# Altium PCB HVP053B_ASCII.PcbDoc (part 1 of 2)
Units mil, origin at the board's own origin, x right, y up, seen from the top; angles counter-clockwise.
Board outline 3600 x 3000 mil, 4 copper layers (Top Layer, Signal Layer 1, Signal Layer 2, Bottom Layer), stack 39.6 mil thick; 143 components, 62 nets, 279 pads, 97 vias.
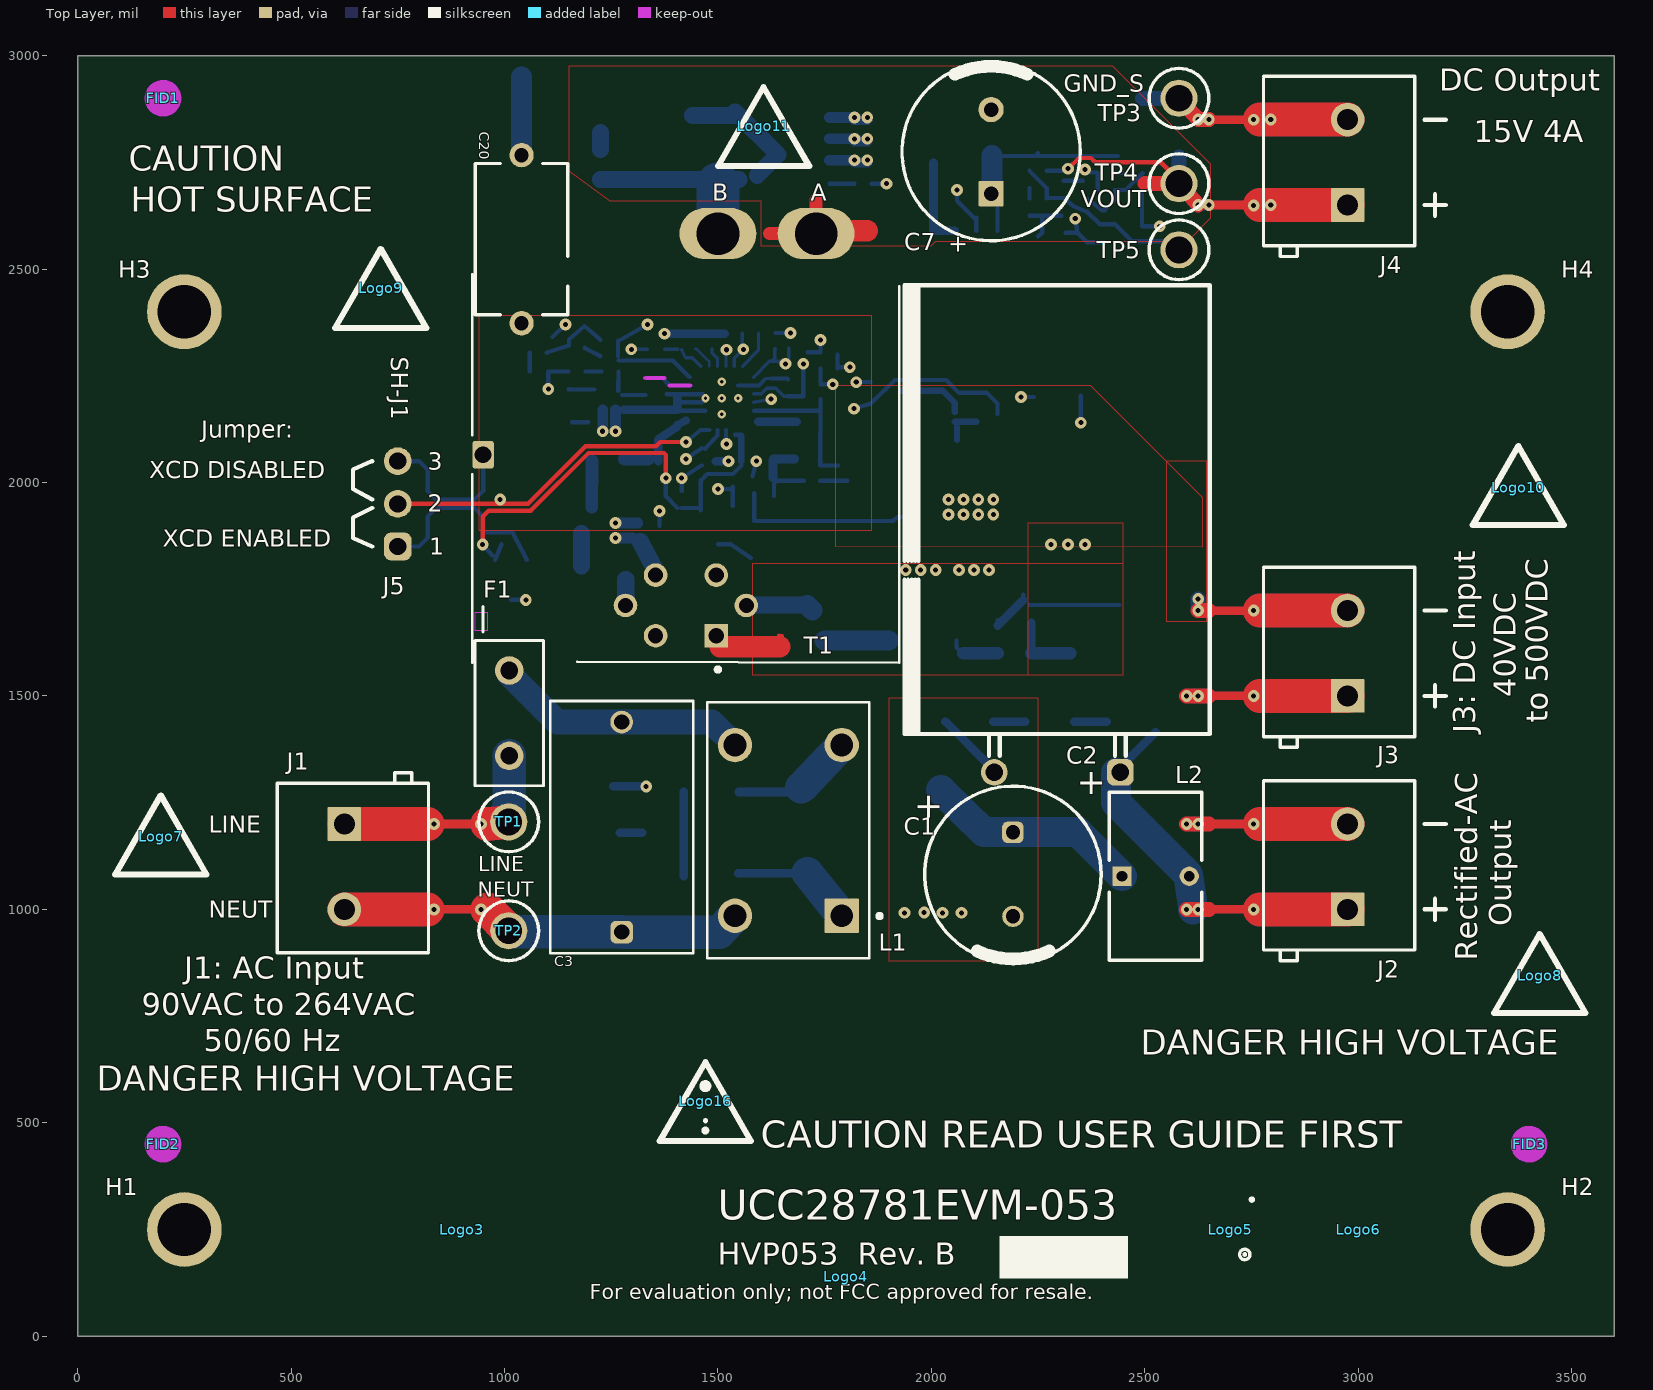
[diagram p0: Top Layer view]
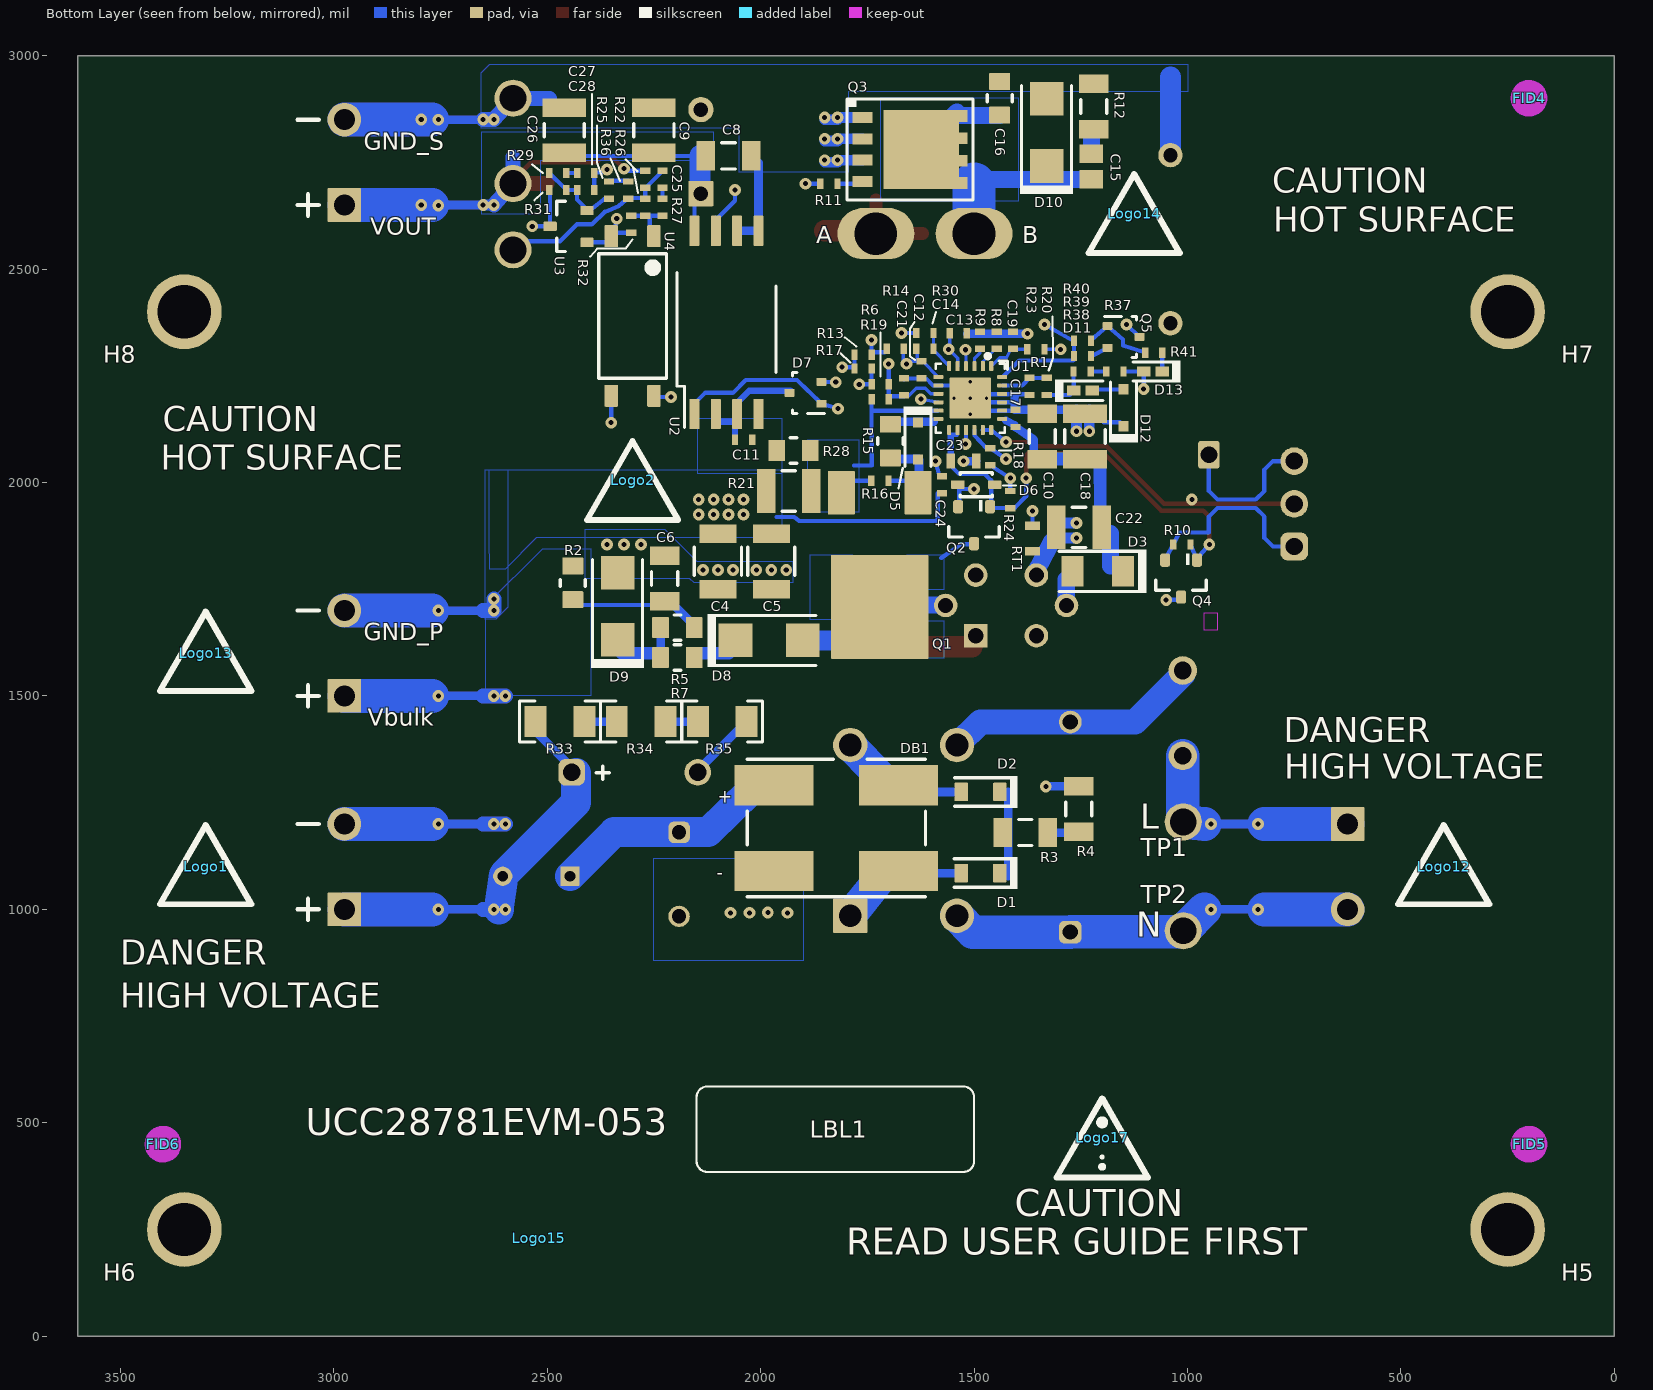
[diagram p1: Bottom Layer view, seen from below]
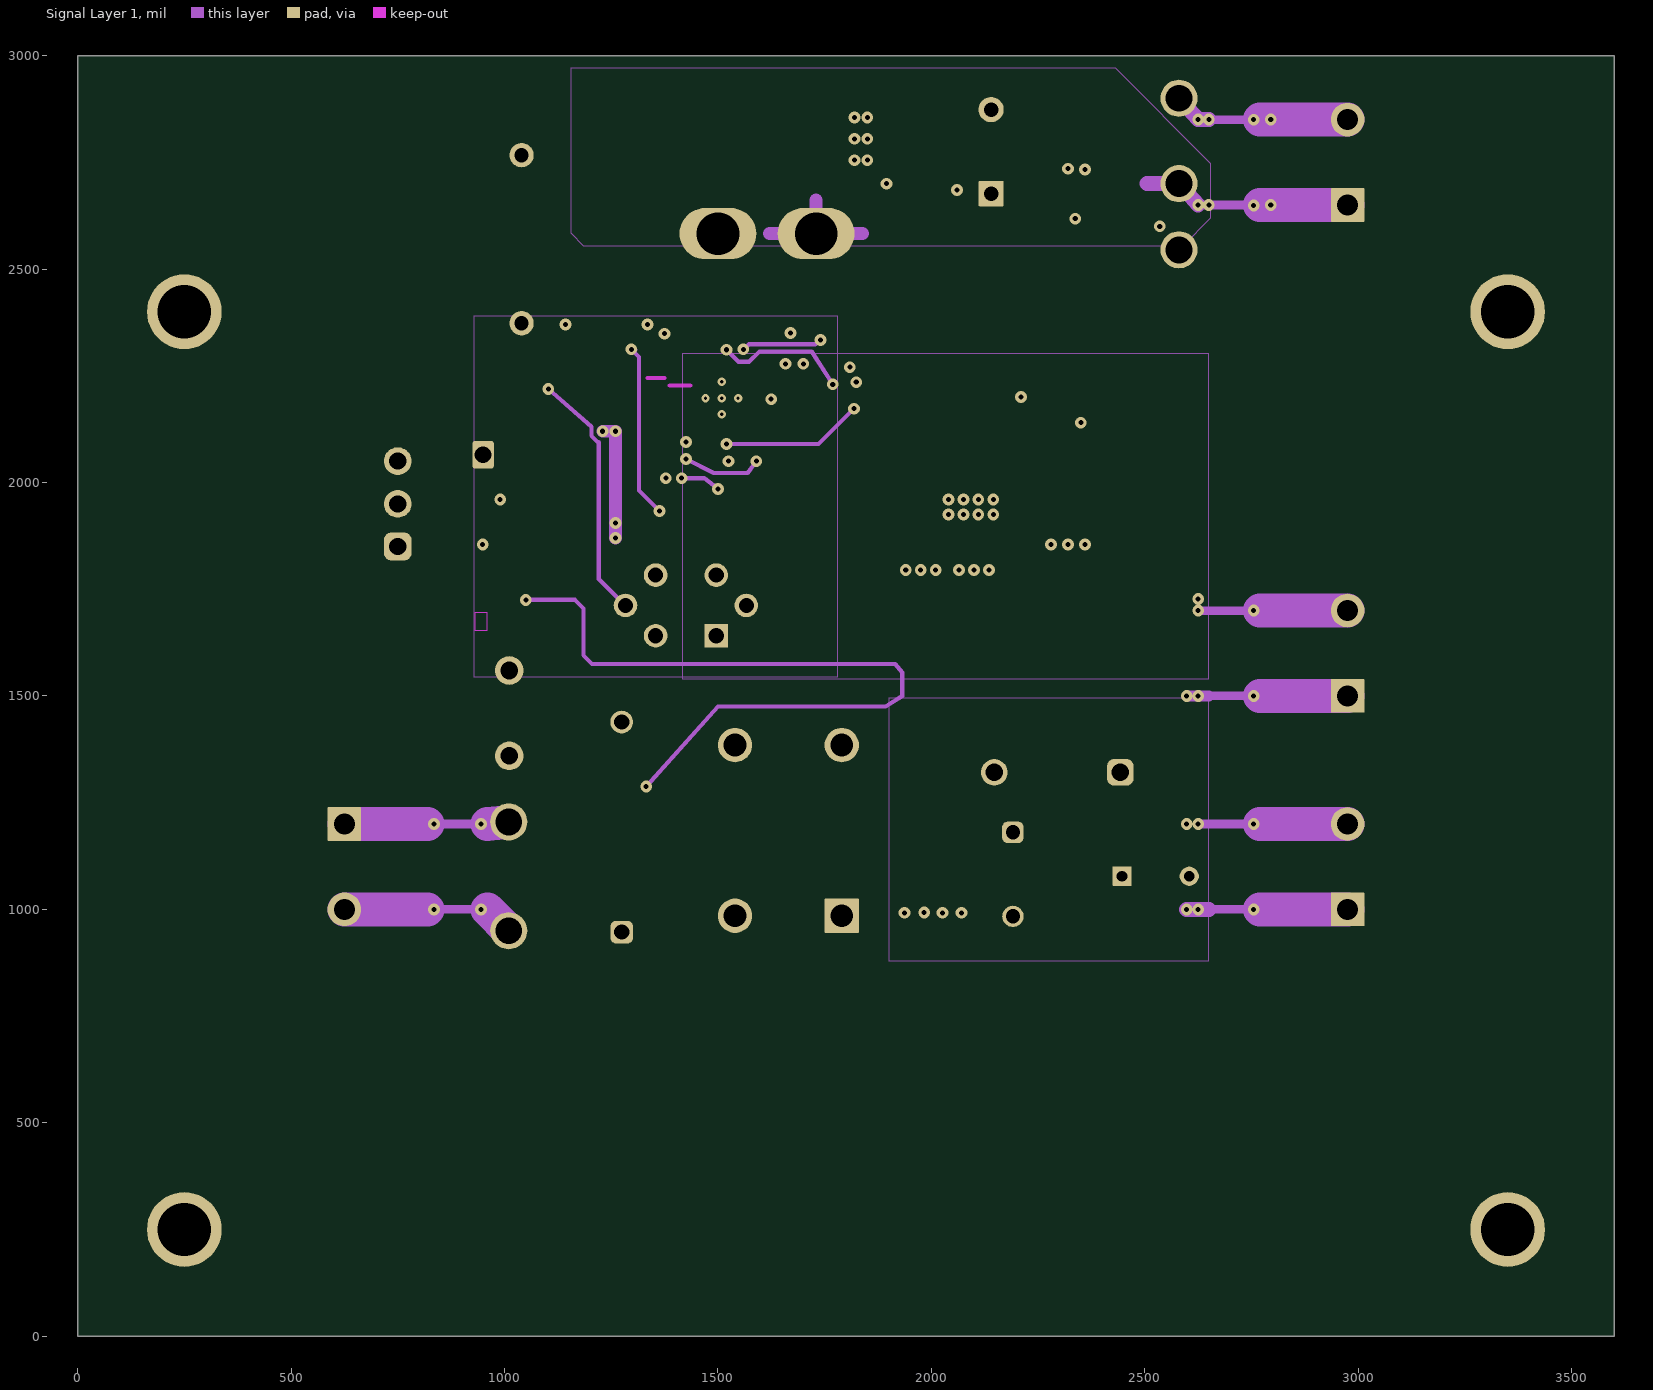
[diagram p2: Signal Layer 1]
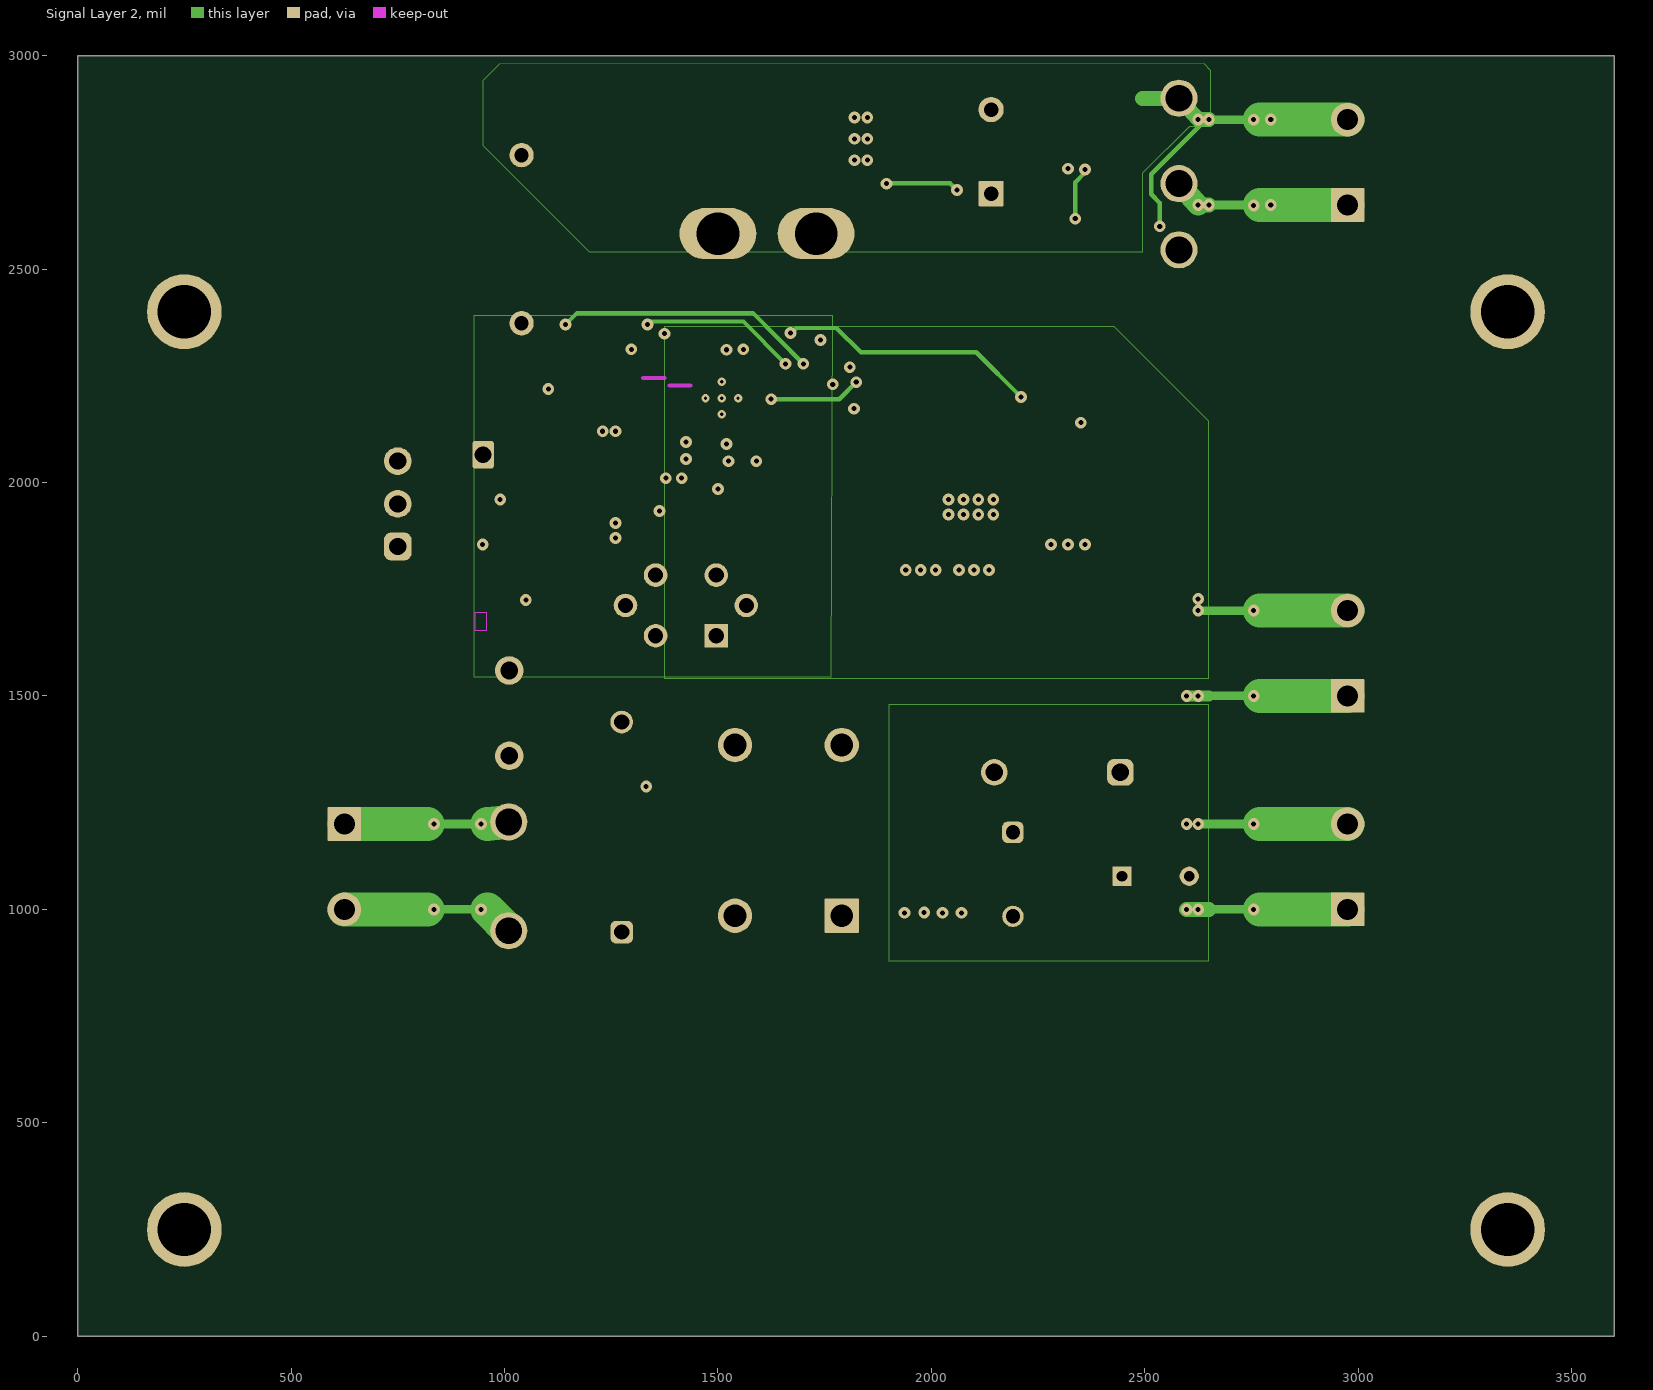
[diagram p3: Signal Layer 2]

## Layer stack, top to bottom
Top Solder: solder mask 0.4, Solder Resist, Dk 3.5
Top Layer: signal copper 1.4
Dielectric 1: prepreg 8, FR-4, Dk 4.2
Signal Layer 1: signal copper 1.4
Dielectric 2: core 18, FR-4, Dk 4.2
Signal Layer 2: signal copper 1.4
Dielectric 3: prepreg 8, FR-4, Dk 4.2
Bottom Layer: signal copper 1.4
Bottom Solder: solder mask 0.4, Solder Resist, Dk 3.5

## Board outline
0,0 3600,0 3600,3000 0,3000

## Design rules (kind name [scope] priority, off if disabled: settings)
AcuteAngle [All] p0: scope1count=1 scope1_0_kind=Board scope1_0_value=Board scope2count=1 scope2_0_kind=Board scope2_0_value=Board commentlength=0 minimum=5.00000000000000E+0000
AcuteAngle [All] p1: minimum=5.00000000000000E+0000 checktracksonly=FALSE
AssemblyTestPointUsage [All] p0: scope1count=1 scope1_0_kind=Board scope1_0_value=Board scope2count=1 scope2_0_kind=Board scope2_0_value=Board commentlength=0
AssemblyTestPointUsage [All] p1: valid=2
AssemblyTestpoint [All] p0: scope1count=1 scope1_0_kind=Board scope1_0_value=Board scope2count=1 scope2_0_kind=Board scope2_0_value=Board commentlength=0
BoardOutlineClearance [All] p0 off: scope1count=1 scope1_0_kind=Board scope1_0_value=Board scope2count=1 scope2_0_kind=Board scope2_0_value=Board commentlength=157 gap=4.53 // Protel DXP Scope 1 Expression Was: OnCopper and Not InComponentClass('Logo') and not InComponentClass('FiducialMark') and not InRegion(1000,500,4000,800)
BoardOutlineClearance BoardOutlineClearance_Poly [All] p0 off: scope1count=1 scope1_0_kind=Board scope1_0_value=Board scope2count=1 scope2_0_kind=Board scope2_0_value=Board commentlength=58 gap=3.94 // Protel DXP Scope 1 Expression Was: OnCopper and InPoly
BoardOutlineClearance BoardOutlineClearance_MountingHoles [All] p0 off: scope1count=1 scope1_0_kind=Board scope1_0_value=Board scope2count=1 scope2_0_kind=Board scope2_0_value=Board commentlength=86 gap=15 // Protel DXP Scope 1 Expression Was: OnCopper and InComponentClass('Mounting Holes')
BoardOutlineClearance BoardOutlineClearance_MountingHoles [OnCopper and InComponentClass('Mounting Holes')] p1: gap=15 ignorepadtopadclearanceinfootprint=FALSE
BoardOutlineClearance BoardOutlineClearance_Poly [OnCopper and InPoly] p2: gap=3.94 ignorepadtopadclearanceinfootprint=FALSE
BoardOutlineClearance [OnCopper and Not InComponentClass('Logo') and not InComponentClass('FiducialMark') and not InRegion(1000,500,4000,800)] p3: gap=4.53 ignorepadtopadclearanceinfootprint=FALSE
Clearance [All] p0 off: scope1count=1 scope1_0_kind=Board scope1_0_value=Board scope2count=1 scope2_0_kind=Board scope2_0_value=Board commentlength=75 gap=6 // Protel DXP Scope 2 Expression Was: not InComponentClass('FiducialMark')
Clearance Clearance_Poly [All] p0 off: scope1count=1 scope1_0_kind=Board scope1_0_value=Board scope2count=1 scope2_0_kind=Board scope2_0_value=Board commentlength=48 gap=8 // Protel DXP Scope 1 Expression Was: InPolygon
Clearance Clearance_Keepouts [All] p0 off: scope1count=1 scope1_0_kind=Board scope1_0_value=Board scope2count=1 scope2_0_kind=Board scope2_0_value=Board commentlength=99 gap=0 // Protel DXP Scope 2 Expression Was: ((IsTrack Or IsArc) And Not InPoly) And IsFree and IsKeepOut
Clearance Clearance_HV [All] p0 off: scope1count=1 scope1_0_kind=NetClass scope1_0_value=HV scope2count=1 scope2_0_kind=Board scope2_0_value=Board commentlength=68 gap=25 // Protel DXP Scope 2 Expression Was: not OnMultiLayer   1mm Clearance
Clearance Clearance_HV [InNetClass('HV') vs not OnMultiLayer] p1: gap=25 ignorepadtopadclearanceinfootprint=TRUE // 1mm Clearance
Clearance Clearance_Keepouts [((IsTrack Or IsArc) And Not InPoly) And IsFree and IsKeepOut vs ((IsTrack Or IsArc) And Not InPoly) And IsFree and IsKeepOut] p2: gap=0 ignorepadtopadclearanceinfootprint=FALSE
Clearance Clearance_Poly [InPolygon] p3: gap=8 ignorepadtopadclearanceinfootprint=FALSE except(0: Arc-Hole Track-Hole SMDPad-Hole THPad-Hole Via-Hole Fill-Hole Poly-Hole Region-Hole Text-Hole)
Clearance [not InComponentClass('FiducialMark') vs not InComponentClass('FiducialMark')] p4: gap=6 ignorepadtopadclearanceinfootprint=FALSE
ComponentClearance [All] p0: scope1count=1 scope1_0_kind=Board scope1_0_value=Board scope2count=1 scope2_0_kind=Board scope2_0_value=Board commentlength=0 gap=8 collisioncheckmode=3
ComponentClearance ComponentClearance_THtoTH [All] p0 off: scope1count=1 scope1_0_kind=Board scope1_0_value=Board scope2count=1 scope2_0_kind=Board scope2_0_value=Board commentlength=54 gap=2 collisioncheckmode=3 // Protel DXP Scope 2 Expression Was: IsThruComponent
ComponentClearance ComponentClearance_THtoSMT [All] p0 off: scope1count=1 scope1_0_kind=Board scope1_0_value=Board scope2count=1 scope2_0_kind=Board scope2_0_value=Board commentlength=53 gap=10 collisioncheckmode=3 // Protel DXP Scope 2 Expression Was: IsSMTComponent
ComponentClearance ComponentClearance_SmallPassives [All] p0 off: scope1count=1 scope1_0_kind=Board scope1_0_value=Board scope2count=1 scope2_0_kind=Board scope2_0_value=Board commentlength=508 gap=8 collisioncheckmode=3 // Protel DXP Scope 2 Expression Was: HasFootprint('0201*') or HasFootprint('0402*') or HasFootprint('0508') or HasFootprint('0603*') or HasFootprint('0612') or HasFootprint('0805*') or HasFootprint('0815*') or HasFootprint('0830*') or HasFootprint('1206*') or HasFootprint('1210*') or HasFootprint('1808*') or HasFootprint('1812*') or HasFootprint('1825*') or HasFootprint('2010*') or HasFootprint('2220*') or HasFootprint('2225*') or HasFootprint('2512*') or HasFootprint('2728*') or HasFootprint('3518*')
ComponentClearance ComponentClearance_MountingHoles [All] p0: scope1count=1 scope1_0_kind=ComponentClass scope1_0_value="Mounting Holes" scope2count=1 scope2_0_kind=Board scope2_0_value=Board commentlength=0 gap=10 collisioncheckmode=3
ComponentClearance ComponentClearance_ScrewToNut [All] p0 off: scope1count=1 scope1_0_kind=Board scope1_0_value=Board scope2count=1 scope2_0_kind=Board scope2_0_value=Board commentlength=71 gap=5 collisioncheckmode=3 // Protel DXP Scope 2 Expression Was: (HasFootprint('Keystone_1902C'))
ComponentClearance ComponentClearance_Logo [All] p0: scope1count=1 scope1_0_kind=ComponentClass scope1_0_value=Logo scope2count=1 scope2_0_kind=Board scope2_0_value=Board commentlength=0 gap=5 collisioncheckmode=3
ComponentClearance ComponentClearance_Shunt [All] p0: scope1count=1 scope1_0_kind=ComponentClass scope1_0_value=Header scope2count=1 scope2_0_kind=ComponentClass scope2_0_value=Shunt commentlength=0 gap=0 collisioncheckmode=3
ComponentClearance ComponentClearance_MountingHoles_FiducialMarks [All] p0: scope1count=1 scope1_0_kind=ComponentClass scope1_0_value="Mounting Holes" scope2count=1 scope2_0_kind=ComponentClass scope2_0_value=FiducialMark commentlength=0 gap=10 collisioncheckmode=3
ComponentClearance ComponentClearance_MountingHoles_FiducialMarks [InComponentClass('Mounting Holes') vs InComponentClass('FiducialMark')] p1: gap=10 collisioncheckmode=3 verticalgap=10 showdistances=FALSE
ComponentClearance ComponentClearance_Shunt [InComponentClass('Header') vs InComponentClass('Shunt')] p2: gap=0 collisioncheckmode=3 verticalgap=0 showdistances=FALSE
ComponentClearance ComponentClearance_Logo [InComponentClass('Logo')] p3: gap=5 collisioncheckmode=3 verticalgap=0 showdistances=FALSE
ComponentClearance ComponentClearance_ScrewToNut [(HasFootprint('NY PMS 440 0025 PH')) vs (HasFootprint('Keystone_1902C'))] p4: gap=5 collisioncheckmode=3 verticalgap=10 showdistances=FALSE
ComponentClearance ComponentClearance_MountingHoles [InComponentClass('Mounting Holes')] p5: gap=10 collisioncheckmode=3 verticalgap=100000 showdistances=FALSE
ComponentClearance ComponentClearance_SmallPassives [HasFootprint('0201*') or HasFootprint('0402*') or HasFootprint('0508') or HasFootprint('0603*') or HasFootprint('0612') or HasFootprint('0805*') or HasFootprint('0815*') or HasFootprint('0830*') or HasFootprint('1206*') or HasFootprint('1210*') or HasFootprint('1808*') or HasFootprint('1812*') or HasFootprint('1825*') or HasFootprint('2010*') or HasFootprint('2220*') or HasFootprint('2225*') or HasFootprint('2512*') or HasFootprint('2728*') or HasFootprint('3518*') vs HasFootprint('0201*') or HasFootprint('0402*') or HasFootprint('0508') or HasFootprint('0603*') or HasFootprint('0612') or HasFootprint('0805*') or HasFootprint('0815*') or HasFootprint('0830*') or HasFootprint('1206*') or HasFootprint('1210*') or HasFootprint('1808*') or HasFootprint('1812*') or HasFootprint('1825*') or HasFootprint('2010*') or HasFootprint('2220*') or HasFootprint('2225*') or HasFootprint('2512*') or HasFootprint('2728*') or HasFootprint('3518*')] p6: gap=8 collisioncheckmode=3 verticalgap=10 showdistances=FALSE
ComponentClearance ComponentClearance_THtoSMT [IsThruComponent vs IsSMTComponent] p7: gap=10 collisioncheckmode=3 verticalgap=30 showdistances=FALSE
ComponentClearance ComponentClearance_THtoTH [IsThruComponent vs IsThruComponent] p8: gap=2 collisioncheckmode=3 verticalgap=30 showdistances=FALSE
ComponentClearance [All] p9: gap=8 collisioncheckmode=3 verticalgap=10 showdistances=FALSE
DiffPairsRouting [All] p0: scope1count=1 scope1_0_kind=Board scope1_0_value=Board scope2count=1 scope2_0_kind=Board scope2_0_value=Board commentlength=0
DiffPairsRouting [All] p1: maxlimit=100 minlimit=10 mostfreqgap=10 toplayer_minwidth=15 toplayer_maxwidth=15 toplayer_prefwidth=15 midlayer1_minwidth=15 midlayer1_maxwidth=15 midlayer1_prefwidth=15 midlayer2_minwidth=15 midlayer2_maxwidth=15 midlayer2_prefwidth=15 bottomlayer_minwidth=15 bottomlayer_maxwidth=15 bottomlayer_prefwidth=15 maxuncoupledlength=1000
FabricationTestPointUsage TestPointUsage [All] p0: scope1count=1 scope1_0_kind=Board scope1_0_value=Board scope2count=1 scope2_0_kind=Board scope2_0_value=Board commentlength=0 valid=2 allowmultiple=FALSE
FabricationTestPointUsage TestPointUsage [All] p1: valid=2 allowmultiple=FALSE
FabricationTestpoint Testpoint [All] p0: scope1count=1 scope1_0_kind=Board scope1_0_value=Board scope2count=1 scope2_0_kind=Board scope2_0_value=Board commentlength=0 side=3 testpointundercomponent=TRUE minsize=40 maxsize=100 preferedsize=60 minholesize=0 maxholesize=40 preferedholesize=32 testpointgrid=1
FabricationTestpoint Testpoint [All] p1: side=3 testpointundercomponent=TRUE minsize=40 maxsize=100 preferedsize=60 minholesize=0 maxholesize=40 preferedholesize=32 testpointgrid=1 allowsidetop=TRUE allowsidebottom=TRUE usegrid=TRUE gridtolerance=0.01
FanoutControl Fanout_Small [All] p0 off: scope1count=1 scope1_0_kind=Board scope1_0_value=Board scope2count=1 scope2_0_kind=Board scope2_0_value=Board commentlength=84 // Protel DXP Scope 1 Expression Was: (CompPinCount < 5)   Fanout_Small (Default Rule)
FanoutControl Fanout_Default [All] p0: scope1count=1 scope1_0_kind=Board scope1_0_value=Board scope2count=1 scope2_0_kind=Board scope2_0_value=Board commentlength=30 // Fanout_Default (Default Rule)
FanoutControl Fanout_SOIC [All] p0 off: scope1count=1 scope1_0_kind=Board scope1_0_value=Board scope2count=1 scope2_0_kind=Board scope2_0_value=Board commentlength=71 // Protel DXP Scope 1 Expression Was: IsSOIC   Fanout_SOIC (Default Rule)
FanoutControl Fanout_BGA [All] p0 off: scope1count=1 scope1_0_kind=Board scope1_0_value=Board scope2count=1 scope2_0_kind=Board scope2_0_value=Board commentlength=69 // Protel DXP Scope 1 Expression Was: IsBGA   Fanout_BGA (Default Rule)
FanoutControl Fanout_LCC [All] p0 off: scope1count=1 scope1_0_kind=Board scope1_0_value=Board scope2count=1 scope2_0_kind=Board scope2_0_value=Board commentlength=69 // Protel DXP Scope 1 Expression Was: IsLCC   Fanout_LCC (Default Rule)
FanoutControl Fanout_LCC [IsLCC] p1: bgadir=Out bgaviamode=Centered fanoutstyle=Auto fanoutdirection=Alternating viagrid=1 // Fanout_LCC (Default Rule)
FanoutControl Fanout_BGA [IsBGA] p2: bgadir=Out bgaviamode=Centered fanoutstyle=Auto fanoutdirection=Alternating viagrid=1 // Fanout_BGA (Default Rule)
FanoutControl Fanout_Default [All] p4: bgadir=Out bgaviamode=Centered fanoutstyle=Auto fanoutdirection=Alternating viagrid=1 // Fanout_Default (Default Rule)
FanoutControl Fanout_Small [(CompPinCount < 5)] p5: bgadir=Out bgaviamode=Centered fanoutstyle=Auto fanoutdirection=OutThenIn viagrid=1 // Fanout_Small (Default Rule)
Height [All] p0: scope1count=1 scope1_0_kind=Board scope1_0_value=Board scope2count=1 scope2_0_kind=Board scope2_0_value=Board commentlength=0
HoleSize [All] p0: scope1count=1 scope1_0_kind=Board scope1_0_value=Board scope2count=1 scope2_0_kind=Board scope2_0_value=Board commentlength=0 absolutevalues=TRUE maxlimit=251 minlimit=7.87 maxpercent=80.000 minpercent=20.000
HoleSize [All] p1: absolutevalues=TRUE maxlimit=251 minlimit=7.87 maxpercent=80.000 minpercent=20.000
HoleToHoleClearance [All] p0: scope1count=1 scope1_0_kind=Board scope1_0_value=Board scope2count=1 scope2_0_kind=Board scope2_0_value=Board commentlength=0
HoleToHoleClearance [All] p1: gap=7.87 allowstackedmicrovias=TRUE
LayerPairs [All] p0: scope1count=1 scope1_0_kind=Board scope1_0_value=Board scope2count=1 scope2_0_kind=Board scope2_0_value=Board commentlength=0 enforce=TRUE
MinimumAnnularRing [All] p0: scope1count=1 scope1_0_kind=Board scope1_0_value=Board scope2count=1 scope2_0_kind=Board scope2_0_value=Board commentlength=0 minimumring=5
MinimumAnnularRing MinimumAnnularRing_ThermalPadVias [All] p0 off: scope1count=1 scope1_0_kind=Board scope1_0_value=Board scope2count=1 scope2_0_kind=Board scope2_0_value=Board commentlength=63 minimumring=5.91 // Protel DXP Scope 1 Expression Was: IsVia and InAnyComponent
MinimumAnnularRing MinimumAnnularRing_ThermalPadVias [IsVia and InAnyComponent] p1: minimumring=5.91
MinimumAnnularRing [All] p2: minimumring=5
MinimumSolderMaskSliver [All] p0: scope1count=1 scope1_0_kind=Board scope1_0_value=Board scope2count=1 scope2_0_kind=Board scope2_0_value=Board commentlength=0
MinimumSolderMaskSliver MinimumSolderMaskSliver_Logo [All] p0: scope1count=1 scope1_0_kind=ComponentClass scope1_0_value=Logo scope2count=1 scope2_0_kind=ComponentClass scope2_0_value=Logo commentlength=0
MinimumSolderMaskSliver MinimumSolderMaskSliver_Logo [InComponentClass('Logo') vs InComponentClass('Logo')] p1: minsoldermaskwidth=0
MinimumSolderMaskSliver [All] p2: minsoldermaskwidth=1
NetAntennae [All] p0: scope1count=1 scope1_0_kind=Board scope1_0_value=Board scope2count=1 scope2_0_kind=Board scope2_0_value=Board commentlength=0
PasteMaskExpansion [All] p0: scope1count=1 scope1_0_kind=Board scope1_0_value=Board scope2count=1 scope2_0_kind=Board scope2_0_value=Board commentlength=0 expansion=0
PlaneClearance [All] p0: scope1count=1 scope1_0_kind=Board scope1_0_value=Board scope2count=1 scope2_0_kind=Board scope2_0_value=Board commentlength=0 clearance=20
PlaneConnect [All] p0: scope1count=1 scope1_0_kind=Board scope1_0_value=Board scope2count=1 scope2_0_kind=Board scope2_0_value=Board commentlength=0 planeconnectstyle=Direct reliefexpansion=10 reliefentries=4 reliefconductorwidth=10 reliefairgap=10
PlaneConnect [All] p1: planeconnectstyle=Direct reliefexpansion=10 reliefentries=4 reliefconductorwidth=10 reliefairgap=10
PolygonConnect [All] p0: scope1count=1 scope1_0_kind=Board scope1_0_value=Board scope2count=1 scope2_0_kind=Board scope2_0_value=Board commentlength=0 connectstyle=Relief reliefconductorwidth=15.75 reliefentries=4 polygonreliefangle="90 Angle"
PolygonConnect [All] p1: thpad.connectstyle=Relief thpad.reliefconductorwidth=15.75 thpad.reliefentries=4 thpad.polygonreliefangle="90 Angle" thpad.airgapwidth=7.87 smdpad.connectstyle=Direct smdpad.reliefconductorwidth=10 smdpad.reliefentries=4 smdpad.polygonreliefangle="90 Angle" smdpad.airgapwidth=10 via.connectstyle=Direct via.reliefconductorwidth=10 via.reliefentries=4 via.polygonreliefangle="90 Angle" via.airgapwidth=10
RoutingCorners [All] p0: scope1count=1 scope1_0_kind=Board scope1_0_value=Board scope2count=1 scope2_0_kind=Board scope2_0_value=Board commentlength=0 cornerstyle=45-Degree minsetback=100 maxsetback=100
RoutingLayers [All] p0: scope1count=1 scope1_0_kind=Board scope1_0_value=Board scope2count=1 scope2_0_kind=Board scope2_0_value=Board commentlength=0 top layer=Automatic mid layer 1=Automatic mid layer 2=Automatic bottom layer=Automatic
RoutingPriority [All] p0: scope1count=1 scope1_0_kind=Board scope1_0_value=Board scope2count=1 scope2_0_kind=Board scope2_0_value=Board commentlength=0
RoutingTopology [All] p0: scope1count=1 scope1_0_kind=Board scope1_0_value=Board scope2count=1 scope2_0_kind=Board scope2_0_value=Board commentlength=0 topology=Shortest
RoutingVias [All] p0: scope1count=1 scope1_0_kind=Board scope1_0_value=Board scope2count=1 scope2_0_kind=Board scope2_0_value=Board commentlength=0 holewidth=16 width=34 viastyle="Through Hole" minholewidth=7.87 minwidth=26 maxholewidth=40 maxwidth=65
RoutingVias ThermalPadVias [All] p0 off: scope1count=1 scope1_0_kind=Board scope1_0_value=Board scope2count=1 scope2_0_kind=Board scope2_0_value=Board commentlength=63 holewidth=7.87 width=19.68 viastyle="Through Hole" minholewidth=7.87 minwidth=19.68 maxholewidth=12.99 maxwidth=23.62 // Protel DXP Scope 1 Expression Was: IsVia and InAnyComponent
RoutingVias ThermalPadVias [IsVia and InAnyComponent] p1: holewidth=7.87 width=19.68 viastyle="Through Hole" minholewidth=7.87 minwidth=19.68 maxholewidth=12.99 maxwidth=23.62
RoutingVias [All] p2: holewidth=16 width=34 viastyle="Through Hole" minholewidth=7.87 minwidth=26 maxholewidth=40 maxwidth=65
ShortCircuit [All] p0: scope1count=1 scope1_0_kind=Board scope1_0_value=Board scope2count=1 scope2_0_kind=Board scope2_0_value=Board commentlength=0 allowed=FALSE
SilkToBoardRegionClearance [All] p0 off: scope1count=1 scope1_0_kind=Board scope1_0_value=Board scope2count=1 scope2_0_kind=Board scope2_0_value=Board commentlength=130 // Protel DXP Scope 1 Expression Was: Not ((IsComment or IsDesignator) And (Hide <> 'False')) and not InRegion(1000,500,4000,800)
SilkToBoardRegionClearance [Not ((IsComment or IsDesignator) And (Hide <> 'False')) and not InRegion(1000,500,4000,800)] p1:
SilkToSilkClearance [All] p0: scope1count=1 scope1_0_kind=Board scope1_0_value=Board scope2count=1 scope2_0_kind=Board scope2_0_value=Board commentlength=0
SilkToSilkClearance SilkToSilkClearance_Pb-FreeLogo [All] p0 off: scope1count=1 scope1_0_kind=Board scope1_0_value=Board scope2count=1 scope2_0_kind=Board scope2_0_value=Board commentlength=120 // Protel DXP Scope 2 Expression Was: (HasFootprint('Pb-Free_Overlay_Medium') OR HasFootprint('Pb-Free_Overlay_Small'))
SilkToSilkClearance SilkToSilkClearance_Pb-FreeLogo [(HasFootprint('Pb-Free_Overlay_Medium') OR HasFootprint('Pb-Free_Overlay_Small')) vs (HasFootprint('Pb-Free_Overlay_Medium') OR HasFootprint('Pb-Free_Overlay_Small'))] p1: silktosilkclearance=0
SilkToSilkClearance [All] p2: silktosilkclearance=0.5
SilkToSolderMaskClearance "Silk to Solder Mask Opening" [All] p0: scope1count=1 scope1_0_kind=Board scope1_0_value=Board scope2count=1 scope2_0_kind=Board scope2_0_value=Board commentlength=0
SilkToSolderMaskClearance SilkToComponentPadClearance [All] p0 off: scope1count=1 scope1_0_kind=Board scope1_0_value=Board scope2count=1 scope2_0_kind=Board scope2_0_value=Board commentlength=63 // Protel DXP Scope 1 Expression Was: IsPad and InAnycomponent
SilkToSolderMaskClearance SilkToComponentPadClearance [IsPad and InAnycomponent] p1: minsilkscreentomaskgap=0.5 clearancetoexposedcopper=TRUE
SilkToSolderMaskClearance "Silk to Solder Mask Opening" [All] p2: minsilkscreentomaskgap=0 clearancetoexposedcopper=FALSE
SolderMaskExpansion [All] p0: scope1count=1 scope1_0_kind=Board scope1_0_value=Board scope2count=1 scope2_0_kind=Board scope2_0_value=Board commentlength=0 expansion=1.97
SolderMaskExpansion [All] p1: expansion=1.97
UnRoutedNet [All] p0: scope1count=1 scope1_0_kind=Board scope1_0_value=Board scope2count=1 scope2_0_kind=Board scope2_0_value=Board commentlength=0
UnpouredPolygon [All] p0: scope1count=1 scope1_0_kind=Board scope1_0_value=Board scope2count=1 scope2_0_kind=Board scope2_0_value=Board commentlength=0
Width [All] p0: scope1count=1 scope1_0_kind=Board scope1_0_value=Board scope2count=1 scope2_0_kind=Board scope2_0_value=Board commentlength=0 maxlimit=100 minlimit=5 preferedwidth=10
Width [All] p1: maxlimit=100 minlimit=5 preferedwidth=10 checkconnectedcopper=TRUE
14 further rules are at their usual default settings.

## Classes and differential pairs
component class "Mounting Holes": H1 H2 H3 H4
component class Logo: Logo3 Logo15
component class Label: LBL1
component class Header: J5
component class FiducialMark: FID1 FID2 FID3 FID4 FID5 FID6
component class AssemblyNote: ZZ1 ZZ2 ZZ3 ZZ4
component class HVP053B_Hardware: !PCB1 FID1 FID2 FID3 FID4 FID5 FID6 H1 H2 H3 H4 H5 H6 H7 H8 LBL1 Logo3 Logo4 Logo5 Logo6 Logo7 Logo8 Logo9 Logo10 Logo11 Logo12 Logo13 Logo14 Logo15 Logo17 ZZ1 ZZ2 ZZ3 ZZ4
net class Secondary: GND_S
net class Primary: GND_P
net class HV: NetC1_1 NetQ4_3 Vbulk Vbulk0 Vswn
component class HVP053B_sheet1: C1 C2 C3 C4 C5 C6 C7 C8 C9 C10 C11 C12 C13 C14 C15 C16 C17 C18 C19 C20 C21 C22 C23 C24 C25 C26 C27 C28 C? D1 D2 D3 D5 D6 D7 D8 D9 D10 D11 D12 D13 D? DB1 F1 J1 J2 J3 J4 J5 L1 L2 LOGO1 LOGO2 Logo16 Q1 Q2 Q3 Q4 Q5 Q? R1 R2 R3 R4 R5 R6 R7 R8 R9 R10 R11 R12 R13 R14 R15 R16 R17 R18 R19 R20 R21 R22 R23 R24 R25 R26 R27 R28 R29 R30 R31 R32 R33 R34 R35 R36 R37 R38 R39 R40 R41 R? RT1 SH-J1 T1 TP1 TP2 TP3 TP4 TP5 TP? U1 U2 U3 U4 U?

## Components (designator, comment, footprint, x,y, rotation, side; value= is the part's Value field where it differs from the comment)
C1 "UVC2G150MPD" UVC_1000x1600 2191,1082 r270 top
C2 "400BXW82MEFR18X25" Rubycon_1800x2500_HD 2295,1321 r180 top locked
C3 "890324024003" WCAP-FTX2_1500x850 1274.58,1192.8 r90 top
C4 "C1210C104KBRAC7800" 1210_280 2100,1815 r270 bottom
C5 "C1210C104KBRAC7800" 1210_280 1975,1815 r270 bottom
C6 "GRM31BR72J102KW01L" 1206L 2225,1775 r270 bottom
C7 "APSG200ELL681MJB5S" PSG_1000x1150 2140,2775 r90 top
C8 "C1206C106J3RACAUTO" 1206_180L 2075,2765 r180 bottom
C9 "GRM32ER71E226KE15L" 1210_270L 2250,2825 r90 bottom
C10 "C3216X5R1H106K160AB" 1206_180L 1340,2108 r90 bottom
C11 "GRM155R71H104ME14D" 0402S 2040,2100 r180 bottom
C12 "GRM155R71C224KA12D" 0402S 1623,2264 r270 bottom
C13 "GRM155R71H331KA01D" 0402S 1537.14,2349.3 r180 bottom
C14 "GRM155R71H331KA01D" 0402S 1615,2313 r180 bottom
C15 "GRM21AR72E102KW01D" 0805L 1225,2740 r270 bottom
C16 "GRM21AR72E152KW01D" 0805_HV1 1440,2900 r90 bottom
C17 "GRM155R71H104ME14D" 0402S 1403,2150 r90 bottom
C18 "GMK325BJ226MM-P" 1210L 1240,2108 r270 bottom
C19 "GRM1555C1H101JA01D" 0402S 1409,2333 r270 bottom
C20 "C921U222MVVDBA7317" C900_9x13 1040,2570 r270 top locked
C21 "GRM1555C1H101JA01D" 0402S 1664,2224 r90 bottom
C22 "GMK325BJ226MM-P" 1210L 1254.15,1895 r180 bottom
C23 "CGA3E1X7R1V105K080AC" 0603S 1525,2050 r180 bottom
C24 "GCM1555C1H220JA16D" 0402S 1575,1995 r90 bottom
C25 "GRM155R71H153KA12D" 0402S 2230,2710 r90 bottom
C26 "GRM32ER71E226KE15L" 1210_270L 2460,2825 r90 bottom
C27 "GRM155R71H103KA88D" 0402S 2410,2725 r180 bottom
C28 "GCM1555C1H220JA16D" 0402S 2410,2685 r0 bottom
D1 "RFU02VSM6STR" TUMD2SM 1485,1085 r0 bottom
D2 "RFU02VSM6STR" TUMD2SM 1484.81,1275 r0 bottom
D3 "CSFMT104-HF" SOD-123H 1210,1792 r0 bottom
D5 "BAS316,115" SOD-323 1631,2097 r270 bottom
D6 "CDSOD323-T18C" FP-CDSOD323-T18C_SOD323-MFG 1495,1995 r180 bottom
D7 "BAS40W-05-7-F" SOT-323 1895,2210 r0 bottom
D8 "MRA4007T3G" SMA 1980,1630 r180 bottom
D9 "SMAJ150A" SMA 2335,1710 r90 bottom
D10 "SMAJ120A" SMA 1330,2820 r90 bottom
D11 "1N4148X-TP" SOD-523 1245,2215 r180 bottom
D12 "SZMM3Z27VST1G" SOD-323 1150,2175 r90 bottom
D13 "BZT585B39T-7" SOD-523 1081,2260 r0 bottom
DB1 "Z4DGP406L-HF" Z4-D 1822.57,1190.39 r180 bottom
F1 "39213150000" FUSE_392 1011.02,1459.54 r270 top
FID1 "Fiducial" Fiducial6.4-20 200,2900 r0 top locked
FID2 "Fiducial" Fiducial6.4-20 200,450 r0 top locked
FID3 "Fiducial" Fiducial6.4-20 3400,450 r0 top locked
FID4 "Fiducial" Fiducial6.4-20 200,2900 r180 bottom locked
FID5 "Fiducial" Fiducial6.4-20 200,450 r180 bottom locked
FID6 "Fiducial" Fiducial6.4-20 3400,450 r180 bottom locked
H1 "NY PMS 440 0025 PH" "NY PMS 440 0025 PH" 250,250 r0 top
H2 "NY PMS 440 0025 PH" "NY PMS 440 0025 PH" 3350,250 r0 top
H3 "NY PMS 440 0025 PH" "NY PMS 440 0025 PH" 250,2400 r0 top
H4 "NY PMS 440 0025 PH" "NY PMS 440 0025 PH" 3350,2400 r0 top
H5 "1902C" Keystone_1902C 250,250 r0 bottom
H6 "1902C" Keystone_1902C 3350,250 r0 bottom
H7 "1902C" Keystone_1902C 250,2400 r0 bottom
H8 "1902C" Keystone_1902C 3350,2400 r0 bottom
J1 "ED120/2DS" On-Shore_ED120_2DS 625,1100 r270 top
J2 "ED120/2DS" On-Shore_ED120_2DS 2975,1100 r90 top
J3 "ED120/2DS" On-Shore_ED120_2DS 2975,1600 r90 top
J4 "ED120/2DS" On-Shore_ED120_2DS 2975,2750 r90 top
J5 "TSW-103-07-G-S" TSW-103-07-G-S 750,1950 r90 top
L1 "RLTI-1387" FP-RLTI-1387_PTH_CMC_0IN38_0IN60-MFG 1665,1185 r90 top
L2 "7447052" FP-7447052_PTH_D10MM0-MFG 2525.33,1077.65 r90 top
LBL1 "THT-14-423-10" Label_650x200 1825,485 r180 bottom
Logo1 "DANGER HIGH VOLTAGE" IEC_HighVoltage_Small 3300,1100 r180 bottom
Logo2 "CAUTION HOT SURFACE" IEC_HotSurface_Small 2300,2005 r180 bottom
Logo3 "Texas Instruments + Symbol" TI_Stacked_Overlay_Small 900,250 r0 top
Logo4 "FCC disclaimer" FCC_disclaimer 1800,140 r0 top
Logo5 "WEEE logo" WEEE_Minimum 2700,250 r0 top
Logo6 "CE Mark" CE_Mark_5mm 3000,250 r0 top
Logo7 "DANGER HIGH VOLTAGE" IEC_HighVoltage_Small 195,1170 r0 top
Logo8 "DANGER HIGH VOLTAGE" IEC_HighVoltage_Small 3425,845 r0 top
Logo9 "CAUTION HOT SURFACE" IEC_HotSurface_Small 710,2455 r0 top
Logo10 "DANGER HIGH VOLTAGE" IEC_HighVoltage_Small 3375,1988 r0 top
Logo11 "CAUTION HOT SURFACE" IEC_HotSurface_Small 1607,2834 r0 top
Logo12 "DANGER HIGH VOLTAGE" IEC_HighVoltage_Small 400,1100 r180 bottom
Logo13 "DANGER HIGH VOLTAGE" IEC_HighVoltage_Small 3300,1600 r180 bottom
Logo14 "CAUTION HOT SURFACE" IEC_HotSurface_Small 1125,2630.02 r180 bottom
Logo15 "Texas Instruments + Symbol" TI_Stacked_Overlay_Small 2520,230 r180 bottom
Logo16 "CAUTION.  READ USER GUIDE BEFORE USE" IEC_Caution_Small 1470.58,550 r0 top
Logo17 "CAUTION.  READ USER GUIDE BEFORE USE" IEC_Caution_Small 1200,465 r180 bottom
Q1 "IPD80R600P7ATMA1" DPAK 1721.2,1842.41 r270 bottom
Q2 "CPC3982TTR" SOT-23L 1500,1900 r270 bottom
Q3 "BSC093N15NS5ATMA1" PG-TDSON-8 1650,2780 r180 bottom
Q4 "BSS126H6327XTSA2" SOT-23L 1015,1775 r270 bottom
Q5 "MMST3906-7-F" SOT-323 1150.02,2341 r180 bottom
R1 "CRCW04023K32FKED" 0402S 1355,2312 r0 bottom
R2 "CRCW0805470KJNEA" 0805_HV1 2440,1765 r90 bottom
R3 "CRCW120613K0JNEA" 1206L 1380,1180 r180 bottom
R4 "CRCW120613K0JNEA" 1206L 1255,1235 r90 bottom
R5 "CRCW080515R0JNEA" 0805_HV1 2195,1660 r180 bottom
R6 "CRCW04021M00JNED" 0402S 1720,2230 r180 bottom
R7 "CRCW080515R0JNEA" 0805_HV1 2195,1590 r0 bottom
R8 "CRCW0402169KFKED" 0402S 1446.59,2332.88 r270 bottom
R9 "CRCW040293K1FKED" 0402S 1485.96,2332.88 r270 bottom
R10 "CRCW04021M00JNED" 0402S 1013,1855 r180 bottom
R11 "CRCW040210R0JNED" 0402S 1840,2700 r180 bottom
R12 "CRCW120610R0JNEA" 1206L 1220,2880.81 r270 bottom
R13 "CRCW040239K2FKED" 0402S 1760,2299 r0 bottom
R14 "CRCW0402191KFKED" 0402S 1685,2313 r0 bottom
R15 "CRCW0805100RJNEA" 0805_HV1 1696,2097 r270 bottom
R16 "CRCW040210K0FKED" 0402S 1720.41,2003.83 r180 bottom
R17 "CRCW04020000Z0EDHP" 0402S 1760,2267 r180 bottom
R18 "CRCW0402511RFKED" 0402S 1462,2060 r270 bottom
R19 "CRCW0402402RFKED" 0402S 1720,2195 r0 bottom
R20 "CRCW040215K4FKED" 0402S 1330,2225 r90 bottom
R21 "MCR25JZHFLR220" 1210L 1934,1980 r180 bottom
R22 "RC0402JR-070RL" 0402S 2270,2710 r270 bottom
R23 "CRCW04026K98FKED" 0402S 1370,2225 r90 bottom
R24 "CRCW04021M00JNED" 0402S 1415,1960 r270 bottom
R25 "ERJ-2RKF1503X" 0402S 2355,2685 r90 bottom
R26 "CRCW040215K0FKED" 0402S 2270,2645 r90 bottom
R27 "CRCW0402511RFKED" 0402S 2230,2645 r90 bottom
R28 "ERJ-6RQFR68V" 0805_HV1 1923,2075 r0 bottom
R29 "CRCW040210K0FKED" 0402S 2475,2725 r0 bottom
R30 "CRCW040220K0FKED" 0402S 1615,2350 r0 bottom
R31 "CRCW040230K0FKED" 0402S 2475,2685 r0 bottom
R32 "CRCW04025K62FKED" 0402S 2303.15,2605 r90 bottom
R33 "CRCW1206220KJNEA" 1206 2470,1440 r0 bottom
R34 "CRCW1206220KJNEA" 1206 2280,1440 r0 bottom
R35 "CRCW1206220KJNEA" 1206 2090,1440 r0 bottom
R36 "CRCW0402102RFKED" 0402S 2310,2685 r90 bottom
R37 "CRCW04022K10FKED" 0402S 1170,2260 r0 bottom
R38 "CRCW04022K10FKED" 0402S 1247,2260 r0 bottom
R39 "CRCW040227K4FKED" 0402S 1246,2296 r180 bottom
R40 "CRCW04021K00FKED" 0402S 1246,2332 r180 bottom
R41 "CRCW040210K0FKED" 0402S 1079,2304 r180 bottom
RT1 "NCP18WB473J03RB" 0603S 1362.93,1868.9 r270 bottom
SH-J1 "SNT-100-BK-T-H" SNT-100-BK-x-H 750,2000 r90 top
T1 "RLTI-1431" FP-RLTI-1431_PTH8_1IN0_0IN91-MFG 1425,2033 r180 top locked
TP1 "LINE" Keystone5011 1010,1205 r90 top
TP2 "NEUTRAL" Keystone5012 1010,950 r90 top
TP3 "GND_S" Keystone5011 2580,2900 r90 top
TP4 "VOUT" Keystone5012 2580,2700 r90 top
TP5 "VOUT_A" Keystone5012 2580,2545 r90 top
U1 "UCC28781QRTWRQ1" RTW0024B-MFG 1508.96,2197.72 r270 bottom
U2 "UCC5304DWV" DWV0008A 2080,2375 r90 bottom locked
U3 "ATL431AIDBZR" DBZ0003A_L 2450,2600 r0 bottom
U4 "TLP383(GR-TPL,E" FP-TLP383(GR-TPL,E_SO6-4-MFG 2300,2390 r270 bottom locked
ZZ1 "These assemblies are ESD sensitive, ESD precautions shall be observed." AssemblyNote 4000,800 r0 top
ZZ2 "These assemblies must be clean and free from flux and all contaminants. Use of no clean flux is not acceptable." AssemblyNote 4000,600 r0 top
ZZ3 "These assemblies must comply with workmanship standards IPC-A-610 Class 2, unless otherwise specified." AssemblyNote 4000,400 r0 top
ZZ4 "Default installation of XCD configuration jumper SH-J1 to be in \"XCD DISABLED\" position on J5 (across pins 2-3)." AssemblyNote 4000,200 r0 top

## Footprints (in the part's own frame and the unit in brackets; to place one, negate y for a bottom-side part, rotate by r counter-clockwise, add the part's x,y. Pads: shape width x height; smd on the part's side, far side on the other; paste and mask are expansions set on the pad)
0402S [mil] "Based on C0402S footprint from PADS legacy"
  rect 15x24 smd: 1(-20,0) 2(20,0)
0603S [mil]
  rect 20x35 smd: 1(-30,0) 2(30,0)
0805_HV1 [mm] "Custom footprint based on analyzing multiple manufacturer recommendations"
  rrect10% 1x1.25 smd: 1(-1,0) 2(1,0)
  silkscreen extent -0.2,-0.75 0.2,0.75
0805L [mm] "0805 from SM-752 data"
  rect 1.1x1.4 smd: 1(-0.75,0) 2(0.75,0)
1206 [mm] "1206 from SM-752 data"
  rect 1.3x1.85 smd: 1(-1.45,0) 2(1.45,0)
  silkscreen extent -2.4,-1.21 2.4,1.21
1206_180L [mm] "1206_180"
  rect 1.1x1.75 smd: 1(-1.35,0) 2(1.35,0)
  silkscreen extent -0.4,-0.77 0.4,0.77
1206L [mm] "1206 from SM-752 data"
  rect 1.1x1.75 smd: 1(-1.35,0) 2(1.35,0)
  silkscreen extent -0.4,-0.77 0.4,0.77
1210_270L [mm] "1210"
  rect 1.1x2.6 smd: 1(-1.35,0) 2(1.35,0)
  silkscreen extent -0.4,-1.2 0.4,1.2
1210_280 [mm] "SMD, 2-Leads, Body 3.6x2.8mm, Height 2.8mm"
  rect 1.1x2.2 smd: 1(-1.65,0) 2(1.65,0)
  silkscreen extent -0.84,-1.4 0.84,1.4
1210L [mm] "1210 from SM-752 data"
  rect 1.1x2.6 smd: 1(-1.35,0) 2(1.35,0)
  silkscreen extent -0.4,-1.2 0.4,1.2
AssemblyNote [mil] "Assembly Note"
C900_9x13 [mm] "Kemet"
  round 1.45 hole 0.85: 1(-5,0) 2(5,0)
  silkscreen extent -4.5,-2.75 4.5,2.76
CE_Mark_5mm [mil] "Minimum text height for CE Mark"
DBZ0003A_L [mm] "SOT23, 3-Leads, Body 2.9x1.3mm, Pitch 0.95mm, Lead Span 2.4mm, IPC High Density"
  rrect18% 0.8x0.55 smd: 1(-1.1,0.95) 2(-1.1,-0.95) 3(1.1,0)
  silkscreen extent 0.2,-1.5 0.7,1.5
DPAK [mm] "D-PAK, 3-Pads, Body 6.22x6.73mm (max), TO-252AA using nominal STEP model"
  rrect6% 2.6x1.6 smd: 1(-3.4,2.28) 3(-3.4,-2.28)
  rrect2% 6.2x5.8 smd paste-3: 2(3.4,0)
DWV0008A [mm] "SOIC, 8-Leads, Body 5.95x7.6mm (max), Pitch 1.27mm"
  rrect17% 1.8x0.6 smd: 1(-5.45,1.905) 2(-5.45,0.635) 3(-5.45,-0.635) 4(-5.45,-1.905) 5(5.45,-1.905) 6(5.45,-0.635) 7(5.45,0.635) 8(5.45,1.905)
  silkscreen extent -6.25,-2.95 2.98,2.95
FCC_disclaimer [mil]
Fiducial6.4-20 [mil]
  round 25 smd mask+0: 1(0,0)
  Top Layer keep-out circle w46.37: c0,0 r19.68
FP-7447052_PTH_D10MM0-MFG [mm]
  rrect9% 1.15x1.15 hole 0.65 paste-1000: 1(0,2)
  round 1.15 hole 0.65 paste-1000: 2(0,-2)
  silkscreen extent -5,-2.75 5,2.75
FP-CDSOD323-T18C_SOD323-MFG [mm]
  rrect20% 0.8x0.5 smd paste+0 mask+0: 1(-1.1,0) 2(1.1,0)
  silkscreen extent -0.95,-0.72 0.95,0.72
FP-RLTI-1387_PTH_CMC_0IN38_0IN60-MFG [mm]
  rrect5% 2.05x2.05 hole 1.35 paste-1000: 1(-5.08,-3.175)
  round 2.05 hole 1.35 paste-1000: 2(-5.08,3.175) 3(5.08,3.175) 4(5.08,-3.175)
  silkscreen extent -7.62,-5.55 7.62,4.83
FP-RLTI-1431_PTH8_1IN0_0IN91-MFG [mm]
  rrect7% 1.4x1.4 hole 0.9 paste-1000: 1(-1.803,9.957)
  round 1.4 hole 0.9 paste-1000: 2(-3.594,8.153) 3(-1.803,6.35) 5(1.803,9.957) 6(3.594,8.153) 7(1.803,6.35)
  rrect25% 1.27x1.651 hole 1 paste-1000 mask+0: 8(12.065,-0.813)
  oval 4.572x3.048 hole 2.54 paste-1000: A(-7.747,-13.97) B(-1.905,-13.97)
  silkscreen extent -12.7,-11.56 12.7,12.09
FP-TLP383(GR-TPL,E_SO6-4-MFG [mm]
  rrect13% 1.3x0.8 smd paste+0 mask+0: 1(-4.75,1.27) 3(-4.75,-1.27) 4(4.75,-1.27) 6(4.75,1.27)
  silkscreen extent -3.7,-2.02 3.7,2.02
FUSE_392 [mm] "LITTELFUSE"
  round 1.7 hole 1.05: 1(-2.54,0) 2(2.54,0)
  silkscreen extent -4.32,-2.03 4.32,2.03
IEC_Caution_Small [mil]
  silkscreen extent -107,-93 107,92
IEC_HighVoltage_Small [mil]
  silkscreen extent -107,-88 107,97
IEC_HotSurface_Small [mil]
  silkscreen extent -107,-93 107,92
Keystone5011 [mil] "Keystone Multipurpose loops"
  round 87 hole 63: 1(0,0)
  silkscreen extent -70,-70 70,70
Keystone5012 [mil] "Keystone Multipurpose loops"
  round 87 hole 63: 1(0,0)
  silkscreen extent -70,-70 70,70
Keystone_1902C [mil] "Hex Standoff, 4-40 threaded, nylon"
  round 1 on Mech4: 0(0,0)
Label_650x200 [mil] "Thermal Transfer Label"
  round 1 on Mech14: 0(0,0)
  silkscreen extent -325,-100 325,100
"NY PMS 440 0025 PH" [mil] "4-40 nylon screw and mounting hole"
  round 175 hole 125: 1(0,0)
On-Shore_ED120_2DS [mm] "ONSHORE"
  rrect5% 2x2 hole 1.25: 1(-2.54,0)
  round 2 hole 1.25: 2(2.54,0)
  silkscreen extent -5.6,-4 5.12,5
PG-TDSON-8 [mm] "Infineon recommended land pattern"
  rect 1.2x0.65 smd: 1(-2.825,1.905) 2(-2.825,0.635) 3(-2.825,-0.635) 4(-2.825,-1.905)
  rect 0.5x0.7 smd: 5(3.175,-2) 6(3.175,-0.675) 7(3.175,0.675) 8(3.175,2)
  rect 4.5x4.7 smd paste-2.25: 9(0.675,0)
  silkscreen extent -3.74,-3 3.74,3
PSG_1000x1150 [mm] "United Chemi-Con"
  rrect7% 1.5x1.5 hole 0.85: 1(-2.5,0)
  round 1.5 hole 0.85: 2(2.5,0)
  silkscreen extent -5.3,-5.3 5.3,5.3
RTW0024B-MFG [mm]
  rrect42% 0.6x0.24 smd paste+0 mask+0: 1(-1.9,1.25) 2(-1.9,0.75) 3(-1.9,0.25) 4(-1.9,-0.25) 5(-1.9,-0.75) 6(-1.9,-1.25) 13(1.9,-1.25) 14(1.9,-0.75) 15(1.9,-0.25) 16(1.9,0.25) 17(1.9,0.75) 18(1.9,1.25)
  rrect42% 0.24x0.6 smd paste+0 mask+0: 7(-1.25,-1.9) 8(-0.75,-1.9) 9(-0.25,-1.9) 10(0.25,-1.9) 11(0.75,-1.9) 12(1.25,-1.9) 19(1.25,1.9) 20(0.75,1.9) 21(0.25,1.9) 22(-0.25,1.9) 23(-0.75,1.9) 24(-1.25,1.9)
  rrect4% 2.45x2.45 smd paste-1000 mask+0: 25(0,0)
  silkscreen extent -2.62,-2.05 2.05,2.05
Rubycon_1800x2500_HD [mm] "TH, 2-Leads, Dia 18mm, Pin Spacing 7.5mm"
  rrect50% 1.575x1.575 hole 1.05: 1(-3.75,0)
  round 1.575 hole 1.05: 2(3.75,0)
SMA [mm] "Molded Diode, 2-Leads, Body 4.3x2.6mm, IPC Medium Density, based on OnSemi component dimensions and land pattern"
  rect 2x2 smd: 1(-2,0) 2(2,0)
  silkscreen extent -3.66,-1.57 2.79,1.57
SNT-100-BK-x-H [mil] "Shunt Connector, 2x1"
  round 1 on Mech3: 0(0,0)
SOD-123H [mm] "SMT, 2-Leads, Body 3.5x1.6mm"
  rect 1.3x1.8 smd: 1(-1.5,0) 2(1.5,0)
  silkscreen extent -2.9,-1.3 2.3,1.3
SOD-323 [mm] "NXP recommended land pattern"
  rect 0.6x0.6 smd paste-0.05: 1(-1.1,0) 2(1.1,0)
  silkscreen extent -2.06,-0.86 1.53,0.86
SOD-523 [mm] "NXP Semiconductor recommended land pattern, nominal STEP model"
  rect 0.8x0.6 smd paste-0.05: 1(-0.55,0) 2(0.55,0)
  silkscreen extent -1.65,-0.66 1.2,0.66
SOT-23L [mm] "SOT23, 3-Leads, Body 2.9x1.3mm, Pitch 0.95mm, Lead Span 2.5mm, IPC High Density"
  rrect50% 0.8x0.6 smd: 1(-1.1,0.95) 2(-1.1,-0.95) 3(1.1,0)
  silkscreen extent -1.5,-1.5 0.7,1.5
SOT-323 [mm] "Diodes Inc recommended land pattern.  2016-02-24"
  rrect21% 0.6x0.47 smd: 1(-0.95,0.65) 2(-0.95,-0.65) 3(0.95,0)
  silkscreen extent -1.14,-1.22 0.77,1.22
TI_Stacked_Overlay_Small [mil]
TSW-103-07-G-S [mm] "Samtec 100mil, 1x3, 230 mil above insulator"
  rrect50% 1.65x1.65 hole 1.016: 1(-2.54,0)
  round 1.65 hole 1.016: 2(0,0) 3(2.54,0)
TUMD2SM [mm] "SMD, 2-Leads, Body 2x1.4mm"
  rrect12% 0.8x1.1 smd: 1(-1.15,0) 2(1.15,0)
  silkscreen extent -2.2,-0.95 1.55,0.95
UVC_1000x1600 [mm] "TH, 2-Leads, Dia 10mm, Lead Spacing 5mm"
  rrect50% 1.275x1.275 hole 0.85: 1(-2.5,0)
  round 1.275 hole 0.85: 2(2.5,0)
  silkscreen extent -5.25,-5.25 5.25,5.25
WCAP-FTX2_1500x850 [mm] "TH, 2-Leads, Body 15x8.5mm"
  rrect50% 1.35x1.35 hole 0.9: 1(-6.25,0)
  round 1.35 hole 0.9: 2(6.25,0)
WEEE_Minimum [mil] "WEEElie bin"
  silkscreen extent 22,-71 54,74
Z4-D [mm] "SMD, 4-Leads, Body 8.1x10.5mm"
  rect 4.7x2.4 smd: 1(-3.7,2.55) 2(3.7,2.55) 3(3.7,-2.55) 4(-3.7,-2.55)
  silkscreen extent -5.3,-4.07 5.3,4.1

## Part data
C1: library part CMP-0860955-2, "CAP, AL, 15 µF, 400 V, +/- 20%, AEC-Q200 Grade 2, TH"
C2: library part CMP-0084285-1, "CAP, AL, 82 µF, 400 V, +/- 20%, TH"
C3: library part CMP-0084596-1, "CAP, Film, 0.33 µF, X2 275 VAC, +/- 10%, TH"
C4 C5: library part CMP-0009076-1, "CAP, CERM, 0.1 uF, 630 V, +/- 10%, X7R, 1210"
C6: library part CMP-0008909-2, "CAP, CERM, 1000 pF, 630 V, +/- 10%, X7R, 1206"
C7: library part CMP-0012176-3, "CAP, Aluminum Polymer, 680 uF, 20 V, +/- 20%, 0.012 ohm, TH"
C8: library part CMP-0081062-1, "CAP, CERM, 10 µF, 25 V,+/- 5%, X7R, AEC-Q200 Grade 1, 1206"
C9 C26: library part CMP-0009224-2, "CAP, CERM, 22 uF, 25 V, +/- 10%, X7R, 1210"
C10: library part CMP-0008658-2, "CAP, CERM, 10 uF, 50 V, +/- 10%, X5R, 1206"
C11 C17: library part CMP-0006675-2, "CAP, CERM, 0.1 uF, 50 V, +/- 20%, X7R, 0402"
C12: library part CMP-0006648-2, "CAP, CERM, 0.22 uF, 16 V, +/- 10%, X7R, 0402"
C13 C14: library part CMP-0006687-2, "CAP, CERM, 330 pF, 50 V, +/- 10%, X7R, 0402"
C15: library part CMP-0008251-2, "CAP, CERM, 1000 pF, 250 V, +/- 10%, X7R, 0805"
C16: library part CMP-0008252-2, "CAP, CERM, 1500 pF, 250 V, +/- 10%, X7R, 0805"
C18 C22: library part CMP-0085817-1, "CAP, CERM, 22 µF, 35 V,+/- 20%, X5R, 1210"
C19 C21: library part CMP-0006410-2, "CAP, CERM, 100 pF, 50 V, +/- 5%, C0G/NP0, 0402"
C20: library part CMP-0078358-1, "CAP, CERM, 2200 pF, X1 400 VAC/Y1 400 VAC, +/- 20%, Y5V, D9xL13mm"
C23: library part CMP-0007067-4, "CAP, CERM, 1 uF, 35 V, +/- 10%, X7R, AEC-Q200 Grade 1, 0603"
C24 C28: library part CMP-0006348-2, "CAP, CERM, 22 pF, 50 V, +/- 5%, C0G/NP0, AEC-Q200 Grade 1, 0402"
C25: library part CMP-0006679-2, "CAP, CERM, 0.015 uF, 50 V, +/- 10%, X7R, 0402"
C27: library part CMP-0006674-2, "CAP, CERM, 0.01 uF, 50 V, +/- 10%, X7R, 0402"
D1 D2: library part CMP-0080762-2, "Diode, Standard Recovery Rectifier, 600 V, 0.2 A, 2x1.4mm"
D3: library part CMP-0029199-2, "Diode, Superfast Rectifier, 200 V, 1 A, 3.5x1.6mm"
D5: library part CMP-0029006-2, "Diode, Ultrafast, 100 V, 0.25 A, SOD-323"
D6: library part CMP-0087587-1, "Diode, TVS, Bi, 18 V, SOD-323"
D7: library part CMP-0028437-2, "Diode, Schottky, 40 V, 0.2 A, SOT-323"
D8: library part CMP-0077082-2, "Diode, Standard Recovery Rectifier, 1000 V, 1 A, AEC-Q101, SMA"
D9: library part CMP-0084982-1, "Diode, TVS, Uni, 150 V, 243 Vc, 400 W, 1.6 A, SMA"
D10: library part CMP-0084980-1, "Diode, TVS, Uni, 120 V, 193 Vc, 400 W, 2.1 A, SMA"
D11: library part CMP-0076957-3, "Diode, Switching, 75 V, 0.3 A, SOD-523"
D12: library part CMP-0085774-1, "Diode, Zener, 27 V, 300 mW, AEC-Q101, SOD-323"
D13: library part CMP-0005889-5, "Diode, Zener, 39 V, 350 mW, AEC-Q101, SOD-523"
DB1: "Diode, P-N-Bridge, 600 V, 4 A, Z4-D"
F1: library part CMP-0003561-2, "Fuse, 3.15 A, 250VAC/VDC, TH"
FID1 FID2 FID3 FID4 FID5 FID6: library part CMP-0077181-1, "Fiducial mark.  There is nothing to buy or mount."
H1 H2 H3 H4: library part CMP-0003617-1, "Machine Screw, Round, #4-40 x 1/4, Nylon, Philips panhead"
H5 H6 H7 H8: library part CMP-0003610-1, "Standoff, Hex, 0.5\"L #4-40 Nylon"
J1 J2 J3 J4: library part CMP-0074910-1, "Terminal Block, 5.08 mm, 2x1, Brass, TH"
J5: library part CMP-0075407-2, "Header, 100mil, 3x1, Gold, TH"
L1: library part CMP-0092946-1, "Common Mode Choke, 2.3mH 35%, 0.6x0.38x0.75 IN"
L2: library part CMP-0087546-1, "WE-FI Leaded Toroidal Line Choke"
LBL1: library part CMP-0003625-1, "Thermal Transfer Printable Labels, 0.650\" W x 0.200\" H - 10,000 per roll"
Logo1 Logo7 Logo8 Logo10 Logo12 Logo13: library part CMP-0074835-1, "IEC 61010-1 High Voltage Warning"
Logo2 Logo9 Logo11 Logo14: library part CMP-0074837-1, "IEC 61010-1 Hot Surface Warning"
Logo3 Logo15: library part CMP-0074838-1, "Texas Instrument Corporate Signature"
Logo4: library part CMP-0074847-1, "FCC_disclaimer"
Logo5: library part CMP-0074769-1
Logo6: library part CMP-0074844-1
Logo16 Logo17: library part CMP-0074836-1, "IEC 61010-1 Caution Warning"
Q1: library part CMP-0083711-2, "MOSFET, N-CH, 800 V, 8 A, DPAK"
Q2: library part CMP-0081263-2, "MOSFET, N-CH, Depletion Mode, 800 V, SOT-23"
Q3: library part CMP-0001046-2, "MOSFET, N-CH, 150 V, 87 A, PG-TDSON-8"
Q4: library part CMP-0067574-2, "MOSFET, N-CH, Depletion Mode, 100 V, 0.17 A, AEC-Q101, SOT-23"
Q5: library part CMP-0077878-2, "Transistor, PNP, 40 V, 0.2 A, AEC-Q101, SOT-323"
R1: library part CMP-0026333-2, "RES, 3.32 k, 1%, 0.063 W, AEC-Q200 Grade 0, 0402"
R2: library part CMP-0020554-3, "RES, 470 k, 5%, 0.125 W, AEC-Q200 Grade 0, 0805"
R3 R4: library part CMP-0018589-3, "RES, 13 k, 5%, 0.25 W, AEC-Q200 Grade 0, 1206"
R5 R7: library part CMP-0020464-3, "RES, 15, 5%, 0.125 W, AEC-Q200 Grade 0, 0805"
R6 R10 R24: library part CMP-0026859-2, "RES, 1.0 M, 5%, 0.063 W, AEC-Q200 Grade 0, 0402"
R8: library part CMP-0026038-3, "RES, 169 k, 1%, 0.063 W, AEC-Q200 Grade 0, 0402"
R9: library part CMP-0026609-3, "RES, 93.1 k, 1%, 0.063 W, AEC-Q200 Grade 0, 0402"
R11: library part CMP-0026827-3, "RES, 10, 5%, 0.063 W, AEC-Q200 Grade 0, 0402"
R12: library part CMP-0018578-3, "RES, 10, 5%, 0.25 W, AEC-Q200 Grade 0, 1206"
R13: library part CMP-0026327-2, "RES, 39.2 k, 1%, 0.063 W, AEC-Q200 Grade 0, 0402"
R14: library part CMP-0026063-3, "RES, 191 k, 1%, 0.063 W, AEC-Q200 Grade 0, 0402"
R15: library part CMP-0020445-3, "RES, 100, 5%, 0.125 W, AEC-Q200 Grade 0, 0805"
R16 R29 R41: library part CMP-0025958-3, "RES, 10.0 k, 1%, 0.063 W, AEC-Q200 Grade 0, 0402"
R17: library part CMP-0081856-1, "RES, 0, 0%, 0.2 W, AEC-Q200 Grade 0, 0402"
R18 R27: library part CMP-0026436-2, "RES, 511, 1%, 0.063 W, AEC-Q200 Grade 0, 0402"
R19: library part CMP-0026366-2, "RES, 402, 1%, 0.063 W, AEC-Q200 Grade 0, 0402"
R20: library part CMP-0026028-3, "RES, 15.4 k, 1%, 0.063 W, AEC-Q200 Grade 0, 0402"
R21: library part CMP-0015175-2, "RES, 0.22, 1%, 0.5 W, 1210"
R22: library part CMP-0027004-2, "RES, 0, 5%, 0.063 W, 0402"
R23: library part CMP-0026518-2, "RES, 6.98 k, 1%, 0.063 W, AEC-Q200 Grade 0, 0402"
R25: library part CMP-0026669-1, "RES, 150 k, 1%, 0.1 W, AEC-Q200 Grade 0, 0402"
R26: library part CMP-0026027-3, "RES, 15.0 k, 1%, 0.063 W, AEC-Q200 Grade 0, 0402"
R28: library part CMP-0021844-3, "RES, 0.68, 1%, 0.125 W, AEC-Q200 Grade 0, 0805"
R30: library part CMP-0026162-2, "RES, 20.0 k, 1%, 0.063 W, AEC-Q200 Grade 0, 0402"
R31: library part CMP-0078244-2, "RES, 30.0 k, 1%, 0.063 W, AEC-Q200 Grade 0, 0402"
R32: library part CMP-0026467-2, "RES, 5.62 k, 1%, 0.063 W, AEC-Q200 Grade 0, 0402"
R33 R34 R35: library part CMP-0018628-3, "RES, 220 k, 5%, 0.25 W, AEC-Q200 Grade 0, 1206"
R36: library part CMP-0025953-3, "RES, 102, 1%, 0.063 W, AEC-Q200 Grade 0, 0402"
R37 R38: library part CMP-0026229-2, "RES, 2.10 k, 1%, 0.063 W, AEC-Q200 Grade 0, 0402"
R39: library part CMP-0026213-2, "RES, 27.4 k, 1%, 0.063 W, AEC-Q200 Grade 0, 0402"
R40: library part CMP-0026071-3, "RES, 1.00 k, 1%, 0.063 W, AEC-Q200 Grade 0, 0402"
RT1: library part CMP-0002523-3, "Thermistor NTC, 47k ohm, 5%, 0603"
SH-J1: library part CMP-0077139-2, "Shunt, 100mil, Tin plated, Black"
T1: library part CMP-0094252-2, "Transformer FLYBACK for UCC28781EVM-053"
TP1 TP3: library part CMP-0055148-1, "Test Point, Multipurpose, Black, TH"
TP2 TP4 TP5: library part CMP-0055149-1, "Test Point, Multipurpose, White, TH"
U1: library part CMP-0094229-1, "Zero-Voltage-Switching Flyback Controller with Dedicated Synchronous Rectifier Gate-Drive"
U2: library part CMP-0860377-2, "4-A/6-A, Single-Channel Reinforced Isolation Gate Driver with High Noise Immunity, DWV0008A (SOIC-8)"
U3: library part CMP-0066199-1, "2.5V Low Iq Adjustable Precision Shunt Regulator, DBZ0003A (SOT-23-3)"
U4: library part CMP-0087394-2, "Optoisolator Transistor Output 5000Vrms 1 Channel 6-SO"
ZZ1: library part CMP-0077236-1
ZZ2: library part CMP-0077237-1
ZZ3: library part CMP-0077238-1
ZZ4: library part CMP-0003615-1, "This Assembly Note will show in the PcbDoc and associated outputs"

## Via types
v1: diameter 27.56, hole 11.81, Top Layer to Bottom Layer, tented top, 38 vias
v2: diameter 27.56, hole 11.81, Top Layer to Bottom Layer, tented both sides, 34 vias
v3: diameter 27.56, hole 11.81, Top Layer to Bottom Layer, 20 vias
v4: diameter 19.68, hole 7.87, Top Layer to Bottom Layer, 5 vias

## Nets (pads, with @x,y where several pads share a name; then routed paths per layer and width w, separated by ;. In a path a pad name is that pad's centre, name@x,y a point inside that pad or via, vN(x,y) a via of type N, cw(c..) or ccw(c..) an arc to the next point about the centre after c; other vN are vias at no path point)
BUR: C13.1 R13.1 R14.2 U1.5 | length 341.5
  Signal Layer 1 w9.84: v2@1556.4,2311.9 v2(1559.42,2311.9) v2@1562.38,2314.85
  Signal Layer 1 w10: v2(1559.42,2311.9) 1572.52,2324 1728,2324 v2(1740,2334)
  Bottom Layer w7.87: U1.5@1538.49,2272.53 1538.49,2290.97 v2(1559.42,2311.9) 1557.1,2314.23 C13.1@1557.14,2349.3
  Bottom Layer w10: R14.2@1710,2305 1740,2305 v2(1740,2334)
CS: C21.1 Q5.3 R6.2 R19.1 U1.9 | length 865.4
  Signal Layer 2 w10: v2(1143,2370) 1170,2397 1582,2397 v2(1700,2278)
  Bottom Layer w8: U1.9@1583.77,2207.57 1601,2207.57 1614.11,2220.69 1635.37,2220.69 1654.29,2201.77 C21.1@1664.11,2201.77
  Bottom Layer w10: Q5.3@1112.61,2341 v2(1143,2370) ; C21.1@1664,2202 1700,2202 R6.2@1700,2230 v2(1700,2278)
FB: C14.2 R30.1 U1.6 | length 92.7
  Bottom Layer w7.87: U1.6@1558.18,2272.53 1594.9,2309.25 1594.9,2312.88 R30.1@1595,2350
FLT: C19.2 R1.2 U1.1 | length 98.2
  Bottom Layer w7.87: C19.2@1401.98,2311.9 1402.3,2311.58 C19.2@1404.27,2311.58 ; 1423.95,2291.9 1440.38,2291.9 U1.1@1459.75,2272.53
  Bottom Layer w8: R1.2@1375,2312 C19.2@1405.98,2312 ; C19.2@1415,2310.91 1423.95,2291.9
GND_P: C4.1 C5.1 C10.2 C11.2 C12.2 C13.2 C17.2 C18.1 C19.1 C20.2 C21.2 C22.1 C23.2 C24.1 D12.1 J3.2 J5.3 R8.1 R9.1 R13.2 R17.1 R21.1 R23.1 R28.2 RT1.2 T1.7 T1.8 U1.8 U1.20 U1.21 U1.22 U1.25 U2.4 U4.4 | length 3639.5
  Top Layer w20: v3@2630,1700 2770,1700
  Top Layer w35: v3@2625,1699.77 2650,1699.77
  Top Layer w80: 2770,1700 J3.2@2975,1700
  Signal Layer 1 w20: v3@2630,1700 2770,1700
  Signal Layer 1 w30: v1(1230,2120) v1(1260,2120) v1(1260,1870)
  Signal Layer 1 w80: 2770,1700 J3.2@2975,1700
  Signal Layer 2 w20: v3@2630,1700 2770,1700
  Signal Layer 2 w80: 2770,1700 J3.2@2975,1700
  Bottom Layer w7.87: C12.2@1612.58,2243.67 C12.2@1624.99,2243.67
  Bottom Layer w8: 1596.16,2227.25 C12.2@1612.58,2243.67
  Bottom Layer w8.66: U1.21@1434.16,2187.49 U1.21@1434.16,2187.88
  Bottom Layer w10: J5.3@750,2050 800,2050 820,2030.1 820,1980 840,1960 930,1960 950,1980 T1.8@950,2065 ; D12.1@1158,2141 C18.1@1196.18,2141 ; R23.1@1380,2207 U1.25@1465,2207 ; 1405,2188 U1.25@1462.6,2188 ; C17.2@1413.2,2168.2 U1.25@1470,2168.2 ; C13.2@1516.51,2348.67 C13.2@1517.14,2349.3 ; U1.25@1547.35,2227.25 1596.16,2227.25 ; C24.1@1585,1975 1585,1910 1910,1910 1921,1919 1963,1919 ; C12.2@1624.99,2243.67 1662.21,2243.67 C21.2@1664.11,2241.77 ; R17.1@1780,2267 R13.2@1780,2299 ; R17.1@1780,2270 v2(1809,2270) ; v1(2350,2140) U4.4@2350,2202.99
  Bottom Layer w20: C18.1@1280,2170 1405,2170 1405,2201.74 ; v2(1375,2348.67) C13.2@1516.51,2348.67 ; C23.2@1495,2050 v2(1525,2050) ; v3@2630,1700 2770,1700
  Bottom Layer w25: v1(1230,2120) C18.1@1230,2170 ; v1(1260,1870) C22.1@1300,1870 ; v1(1260,1905) C22.1@1312.35,1905 ; v1(1260,2120) C18.1@1260,2170
  Bottom Layer w35: v3(2625,1727) 2625,1699.77 2650,1699.77
  Bottom Layer w40: C22.1@1318,1862 T1.7@1359,1783.75
  Bottom Layer w80: 2770,1700 J3.2@2975,1700
  other v1: 2040,1925 2075,1925 2110,1925 2145,1925 2040,1960 2075,1960 2110,1960 2145,1960
  other v3: 2625,1700 2755,1700
  other v4: 1508.96,2159.54 1470.78,2197.72 1508.96,2197.72 1547.15,2197.72 1508.96,2235.91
